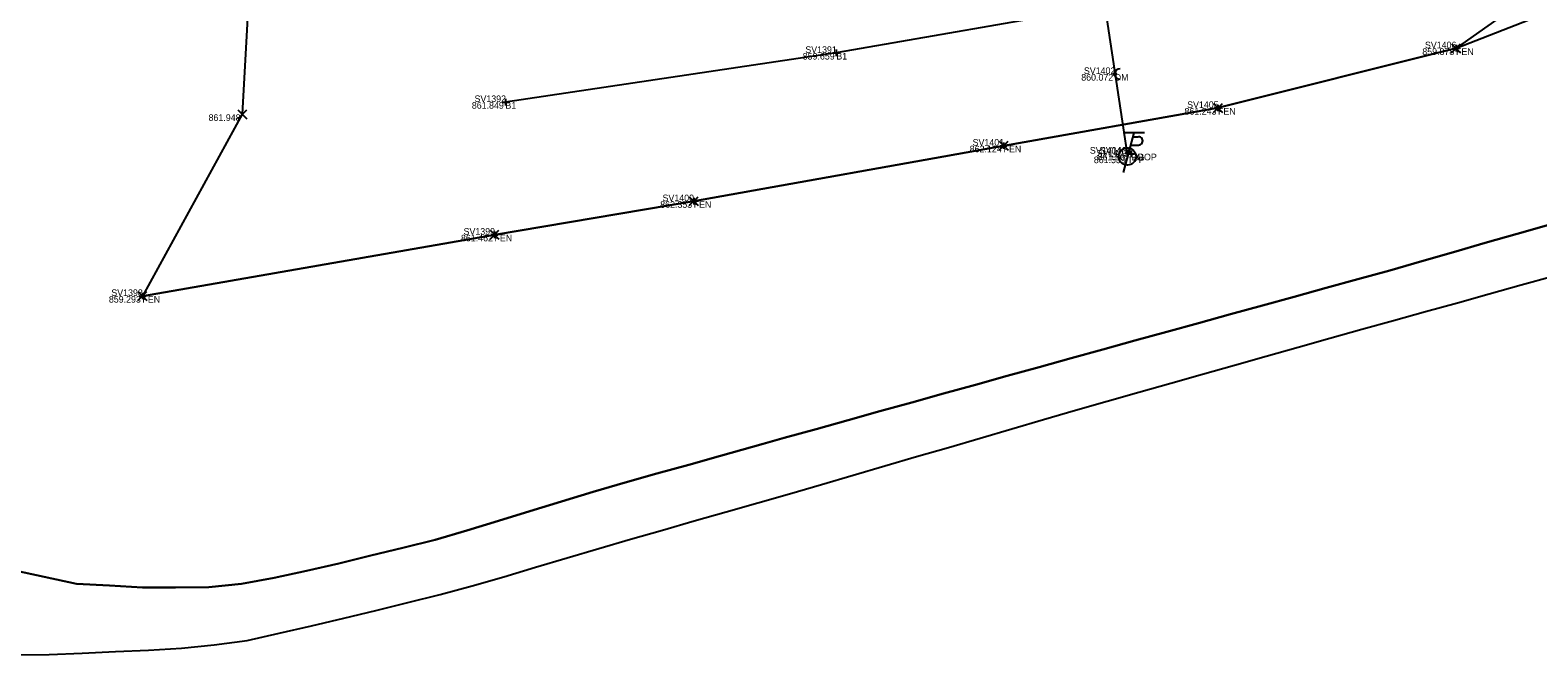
# Model space of a CAD drawing. Extents: x 2125299 to 2129212, y 713100 to 714300.
# Drawn here: x 2128033.5 to 2128261.4, y 713741.2 to 713835.6 of the extents above; entities that cross this region are included whole.
import ezdxf

# ---------------------------------------------------------------- set-up
doc = ezdxf.new("R2010")
doc.units = 0
for name, color, linetype in [('Default', 7, 'Continuous'), ('DT_X_Terrain_Boundary', 7, 'Continuous'), ('PV_X_Field_Drive', 7, 'Continuous'), ('RD_X_Fence', 7, 'Continuous'), ('RW_P_Esmt_TMP', 7, 'Continuous'), ('RW_X_CL_100_Distances', 7, 'Continuous'), ('RW_X_Esmt_CH', 7, 'Continuous'), ('RW_X_Fee_WL', 7, 'Continuous'), ('SV_X_Break_Lines', 7, 'Continuous'), ('SV_X_Mon_Cells_Found', 7, 'Continuous'), ('SV_X_Text_Elevation', 7, 'Continuous'), ('UT_X_Overhead_Telecom_FO', 7, 'Continuous')]:
    doc.layers.add(name, color=color, linetype=linetype)

msp = doc.modelspace()

# ---------------------------------------------------------------- linework, layer by layer
at = {"layer": 'Default'}
for points in [[(2128027.32, 713868.17), (2128036.98, 713870.74), (2128046.65, 713873.31), (2128056.31, 713875.88), (2128065.98, 713878.44), (2128075.64, 713881.03), (2128074.37, 713874.69), (2128066.44, 713838.36), (2128065.59, 713822.89), (2128050.49, 713795.43), (2128103.72, 713804.69), (2128133.83, 713809.76), (2128180.68, 713818.15), (2128213.09, 713823.85), (2128249.08, 713832.87), (2128285.01, 713846.97)], [(2128263.11, 713806.21), (2128258.3, 713804.83), (2128253.5, 713803.45), (2128248.69, 713802.07), (2128243.89, 713800.69), (2128239.08, 713799.31), (2128234.26, 713797.98), (2128229.44, 713796.65), (2128224.62, 713795.33), (2128219.8, 713794), (2128214.98, 713792.67), (2128210.16, 713791.34), (2128205.34, 713790.02), (2128200.52, 713788.69), (2128195.7, 713787.36), (2128190.88, 713786.03), (2128186.06, 713784.69), (2128181.24, 713783.35), (2128176.43, 713782.01), (2128171.61, 713780.67), (2128166.79, 713779.34), (2128161.97, 713778), (2128157.16, 713776.66), (2128152.34, 713775.32), (2128147.52, 713773.97), (2128144.35, 713773.08), (2128142.71, 713772.62), (2128137.89, 713771.27), (2128133.08, 713769.92), (2128128.26, 713768.58), (2128123.45, 713767.23), (2128118.65, 713765.84), (2128113.86, 713764.38), (2128109.08, 713762.92), (2128104.3, 713761.47), (2128099.52, 713760.01), (2128094.73, 713758.57), (2128089.87, 713757.38), (2128085.01, 713756.19), (2128080.16, 713755), (2128075.28, 713753.89), (2128070.4, 713752.83), (2128065.49, 713751.93), (2128060.51, 713751.43), (2128055.51, 713751.37), (2128050.51, 713751.39), (2128045.52, 713751.66), (2128040.53, 713751.94), (2128035.64, 713753), (2128030.76, 713754.05)]]:
    msp.add_lwpolyline(points, dxfattribs=at)
at = {"layer": 'DT_X_Terrain_Boundary'}
msp.add_lwpolyline([(2128031.41, 713741.19), (2128036.41, 713741.26), (2128041.4, 713741.47), (2128046.4, 713741.69), (2128051.39, 713741.91), (2128056.38, 713742.22), (2128061.36, 713742.71), (2128066.31, 713743.34), (2128071.18, 713744.47), (2128076.06, 713745.59), (2128080.92, 713746.75), (2128085.78, 713747.92), (2128090.64, 713749.09), (2128095.49, 713750.31), (2128100.32, 713751.6), (2128105.12, 713752.99), (2128109.92, 713754.42), (2128114.71, 713755.84), (2128119.5, 713757.27), (2128124.29, 713758.69), (2128129.1, 713760.06), (2128133.91, 713761.43), (2128138.72, 713762.8), (2128143.53, 713764.17), (2128148.34, 713765.53), (2128153.14, 713766.93), (2128157.94, 713768.34), (2128162.74, 713769.74), (2128167.53, 713771.15), (2128172.33, 713772.55), (2128177.13, 713773.96), (2128181.93, 713775.37), (2128186.73, 713776.77), (2128191.53, 713778.18), (2128196.34, 713779.54), (2128201.15, 713780.9), (2128205.96, 713782.26), (2128210.77, 713783.62), (2128215.58, 713784.99), (2128220.39, 713786.35), (2128225.2, 713787.71), (2128230.02, 713789.06), (2128234.83, 713790.4), (2128239.65, 713791.74), (2128244.47, 713793.08), (2128249.29, 713794.42), (2128254.1, 713795.76), (2128258.92, 713797.1), (2128263.74, 713798.44)], dxfattribs=at)
at = {"layer": 'PV_X_Field_Drive'}
for points in [[(2128030.76, 713754.05), (2128035.64, 713753), (2128040.53, 713751.94), (2128045.52, 713751.66), (2128050.51, 713751.39), (2128055.51, 713751.37), (2128060.51, 713751.43), (2128065.49, 713751.93), (2128070.4, 713752.83), (2128075.28, 713753.89), (2128080.16, 713755), (2128085.01, 713756.19), (2128089.87, 713757.38), (2128094.73, 713758.57), (2128099.52, 713760.01), (2128104.3, 713761.47), (2128109.08, 713762.92), (2128113.86, 713764.38), (2128118.65, 713765.84), (2128123.45, 713767.23), (2128128.26, 713768.58), (2128133.08, 713769.92), (2128137.89, 713771.27), (2128142.71, 713772.62), (2128147.52, 713773.97), (2128152.34, 713775.32), (2128157.16, 713776.66), (2128161.97, 713778), (2128166.79, 713779.34), (2128171.61, 713780.67), (2128176.43, 713782.01), (2128181.24, 713783.35), (2128186.06, 713784.69), (2128190.88, 713786.03), (2128195.7, 713787.36), (2128200.52, 713788.69), (2128205.34, 713790.02), (2128210.16, 713791.34), (2128214.98, 713792.67), (2128219.8, 713794), (2128224.62, 713795.33), (2128229.44, 713796.65), (2128234.26, 713797.98), (2128239.08, 713799.31), (2128243.89, 713800.69), (2128248.69, 713802.07), (2128253.5, 713803.45), (2128258.3, 713804.83), (2128263.11, 713806.21)], [(2128031.41, 713741.19), (2128036.41, 713741.26), (2128041.4, 713741.47), (2128046.4, 713741.69), (2128051.39, 713741.91), (2128056.38, 713742.22), (2128061.36, 713742.71), (2128066.31, 713743.34), (2128071.18, 713744.47), (2128076.06, 713745.59), (2128080.92, 713746.75), (2128085.78, 713747.92), (2128090.64, 713749.09), (2128095.49, 713750.31), (2128100.32, 713751.6), (2128105.12, 713752.99), (2128109.92, 713754.42), (2128114.71, 713755.84), (2128119.5, 713757.27), (2128124.29, 713758.69), (2128129.1, 713760.06), (2128133.91, 713761.43), (2128138.72, 713762.8), (2128143.53, 713764.17), (2128148.34, 713765.53), (2128153.14, 713766.93), (2128157.94, 713768.34), (2128162.74, 713769.74), (2128167.53, 713771.15), (2128172.33, 713772.55), (2128177.13, 713773.96), (2128181.93, 713775.37), (2128186.73, 713776.77), (2128191.53, 713778.18), (2128196.34, 713779.54), (2128201.15, 713780.9), (2128205.96, 713782.26), (2128210.77, 713783.62), (2128215.58, 713784.99), (2128220.39, 713786.35), (2128225.2, 713787.71), (2128230.02, 713789.06), (2128234.83, 713790.4), (2128239.65, 713791.74), (2128244.47, 713793.08), (2128249.29, 713794.42), (2128254.1, 713795.76), (2128258.92, 713797.1), (2128263.74, 713798.44)]]:
    msp.add_lwpolyline(points, dxfattribs=at)
at = {"layer": 'RD_X_Fence'}
msp.add_lwpolyline([(2128324.53, 713881.58), (2128301.55, 713867.57), (2128272.2, 713849.2), (2128249.08, 713832.87), (2128213.09, 713823.85), (2128180.68, 713818.15), (2128133.83, 713809.76), (2128103.72, 713804.69), (2128050.49, 713795.43)], dxfattribs=at)
at = {"layer": 'RW_X_CL_100_Distances'}
for p, q in [((2128200.37, 713820.11), (2128198.76, 713814.11)), ((2128201.97, 713820.11), (2128198.77, 713820.11)), ((2128199.86, 713818.24), (2128201.06, 713818.24)), ((2128200.21, 713819.51), (2128201.06, 713819.51))]:
    msp.add_line(p, q, dxfattribs=at)
for centre, radius in [((2128197.49, 713828.98), 0.2), ((2128199.4, 713816.51), 1.3)]:
    msp.add_circle(centre, radius, dxfattribs=at)
for centre, radius, start, end in [((2128198.29, 713828.98), 0.8, 90, 270), ((2128201.07, 713818.88), 0.638, 268.8767, 91.1233)]:
    msp.add_arc(centre, radius, start, end, dxfattribs=at)
at = {"layer": 'SV_X_Break_Lines'}
msp.add_lwpolyline([(2128362.17, 713888.6), (2128349.08, 713887.91), (2128324.53, 713881.58), (2128301.55, 713867.57), (2128295.43, 713864.02), (2128280.27, 713864.93), (2128247.09, 713854.32), (2128208.78, 713841.53), (2128155.39, 713832.17), (2128105.37, 713824.74)], dxfattribs=at)
at = {"layer": 'SV_X_Mon_Cells_Found'}
for p, q in [((2128249.08, 713833.37), (2128249.08, 713832.37)), ((2128154.89, 713832.17), (2128155.89, 713832.17)), ((2128155.39, 713832.67), (2128155.39, 713831.67)), ((2128155.39, 713832.17), (2128155.39, 713832.17)), ((2128248.58, 713832.87), (2128249.58, 713832.87)), ((2128249.08, 713832.87), (2128249.08, 713832.87)), ((2128104.87, 713824.74), (2128105.87, 713824.74)), ((2128105.37, 713825.24), (2128105.37, 713824.24)), ((2128105.37, 713824.74), (2128105.37, 713824.74)), ((2128213.09, 713824.35), (2128213.09, 713823.35)), ((2128212.59, 713823.85), (2128213.59, 713823.85)), ((2128213.09, 713823.85), (2128213.09, 713823.85)), ((2128180.18, 713818.15), (2128181.18, 713818.15)), ((2128180.68, 713818.65), (2128180.68, 713817.65)), ((2128180.68, 713818.15), (2128180.68, 713818.15)), ((2128199.98, 713817.44), (2128199.98, 713816.44)), ((2128199.98, 713817.44), (2128199.98, 713816.44)), ((2128199.48, 713816.94), (2128200.48, 713816.94)), ((2128199.48, 713816.94), (2128200.48, 713816.94)), ((2128199.98, 713816.94), (2128199.98, 713816.94)), ((2128199.98, 713816.94), (2128199.98, 713816.94)), ((2128133.33, 713809.76), (2128134.33, 713809.76)), ((2128133.83, 713810.26), (2128133.83, 713809.26)), ((2128133.83, 713809.76), (2128133.83, 713809.76)), ((2128103.22, 713804.69), (2128104.22, 713804.69)), ((2128103.72, 713805.19), (2128103.72, 713804.19)), ((2128103.72, 713804.69), (2128103.72, 713804.69)), ((2128049.99, 713795.43), (2128050.99, 713795.43)), ((2128050.49, 713795.93), (2128050.49, 713794.93)), ((2128050.49, 713795.43), (2128050.49, 713795.43))]:
    msp.add_line(p, q, dxfattribs=at)
at = {"layer": 'SV_X_Text_Elevation'}
for p, q in [((2128248.41, 713832.2), (2128249.75, 713833.53)), ((2128248.41, 713833.53), (2128249.75, 713832.2)), ((2128212.43, 713823.19), (2128213.76, 713824.52)), ((2128212.43, 713824.52), (2128213.76, 713823.19)), ((2128064.92, 713822.22), (2128066.26, 713823.55)), ((2128064.92, 713823.55), (2128066.26, 713822.22)), ((2128180.01, 713817.49), (2128181.35, 713818.82)), ((2128180.01, 713818.82), (2128181.35, 713817.49)), ((2128133.16, 713809.1), (2128134.5, 713810.43)), ((2128133.16, 713810.43), (2128134.5, 713809.1)), ((2128103.06, 713804.03), (2128104.39, 713805.36)), ((2128103.06, 713805.36), (2128104.39, 713804.03)), ((2128049.82, 713794.77), (2128051.15, 713796.1)), ((2128049.82, 713796.1), (2128051.15, 713794.77))]:
    msp.add_line(p, q, dxfattribs=at)
at = {"layer": 'UT_X_Overhead_Telecom_FO'}
msp.add_lwpolyline([(2128144.62, 714178.88), (2128199.4, 713816.51)], dxfattribs=at)

# ---------------------------------------------------------------- texts
at = {"layer": 'RW_P_Esmt_TMP'}
for s, p in [('B1', (2128155.39, 713831.17)), ('FEN', (2128249.08, 713831.87)), ('DM', (2128197.49, 713827.98)), ('B1', (2128105.37, 713823.74)), ('FEN', (2128213.09, 713822.85)), ('FEN', (2128180.68, 713817.15)), ('TPP', (2128199.4, 713815.51)), ('FO', (2128199.98, 713815.94)), ('DROP', (2128199.98, 713815.94)), ('FEN', (2128133.83, 713808.76)), ('FEN', (2128103.72, 713803.69)), ('FEN', (2128050.49, 713794.43))]:
    msp.add_text(s, height=1, dxfattribs=at).set_placement(p)
at = {"layer": 'RW_X_Esmt_CH'}
for s, p in [('SV1406', (2128244.38, 713832.87)), ('SV1391', (2128150.71, 713832.17)), ('SV1402', (2128192.82, 713828.98)), ('SV1392', (2128100.7, 713824.74)), ('SV1405', (2128208.43, 713823.85)), ('SV1401', (2128176, 713818.15)), ('SV1404_1', (2128193.72, 713816.94)), ('SV1403', (2128194.74, 713816.51)), ('SV1404', (2128195.26, 713816.94)), ('SV1400', (2128129.12, 713809.76)), ('SV1399', (2128099.04, 713804.69)), ('SV1398', (2128045.79, 713795.43))]:
    msp.add_text(s, height=1, dxfattribs=at).set_placement(p)
at = {"layer": 'RW_X_Fee_WL'}
for s, p in [('859.659', (2128150.31, 713831.17)), ('859.878', (2128243.98, 713831.87)), ('859.878', (2128243.98, 713831.87)), ('860.072', (2128192.42, 713827.98)), ('861.849', (2128100.29, 713823.74)), ('861.948', (2128060.49, 713821.89)), ('861.243', (2128208.03, 713822.85)), ('861.243', (2128208.03, 713822.85)), ('862.124', (2128175.56, 713817.15)), ('862.124', (2128175.56, 713817.15)), ('861.539', (2128194.32, 713815.51)), ('861.507', (2128194.89, 713815.94)), ('861.507', (2128194.89, 713815.94)), ('862.353', (2128128.77, 713808.76)), ('862.353', (2128128.77, 713808.76)), ('861.462', (2128098.65, 713803.69)), ('861.462', (2128098.65, 713803.69)), ('859.293', (2128045.42, 713794.43)), ('859.293', (2128045.42, 713794.43))]:
    msp.add_text(s, height=1, dxfattribs=at).set_placement(p)

doc.saveas('drawing.dxf')
